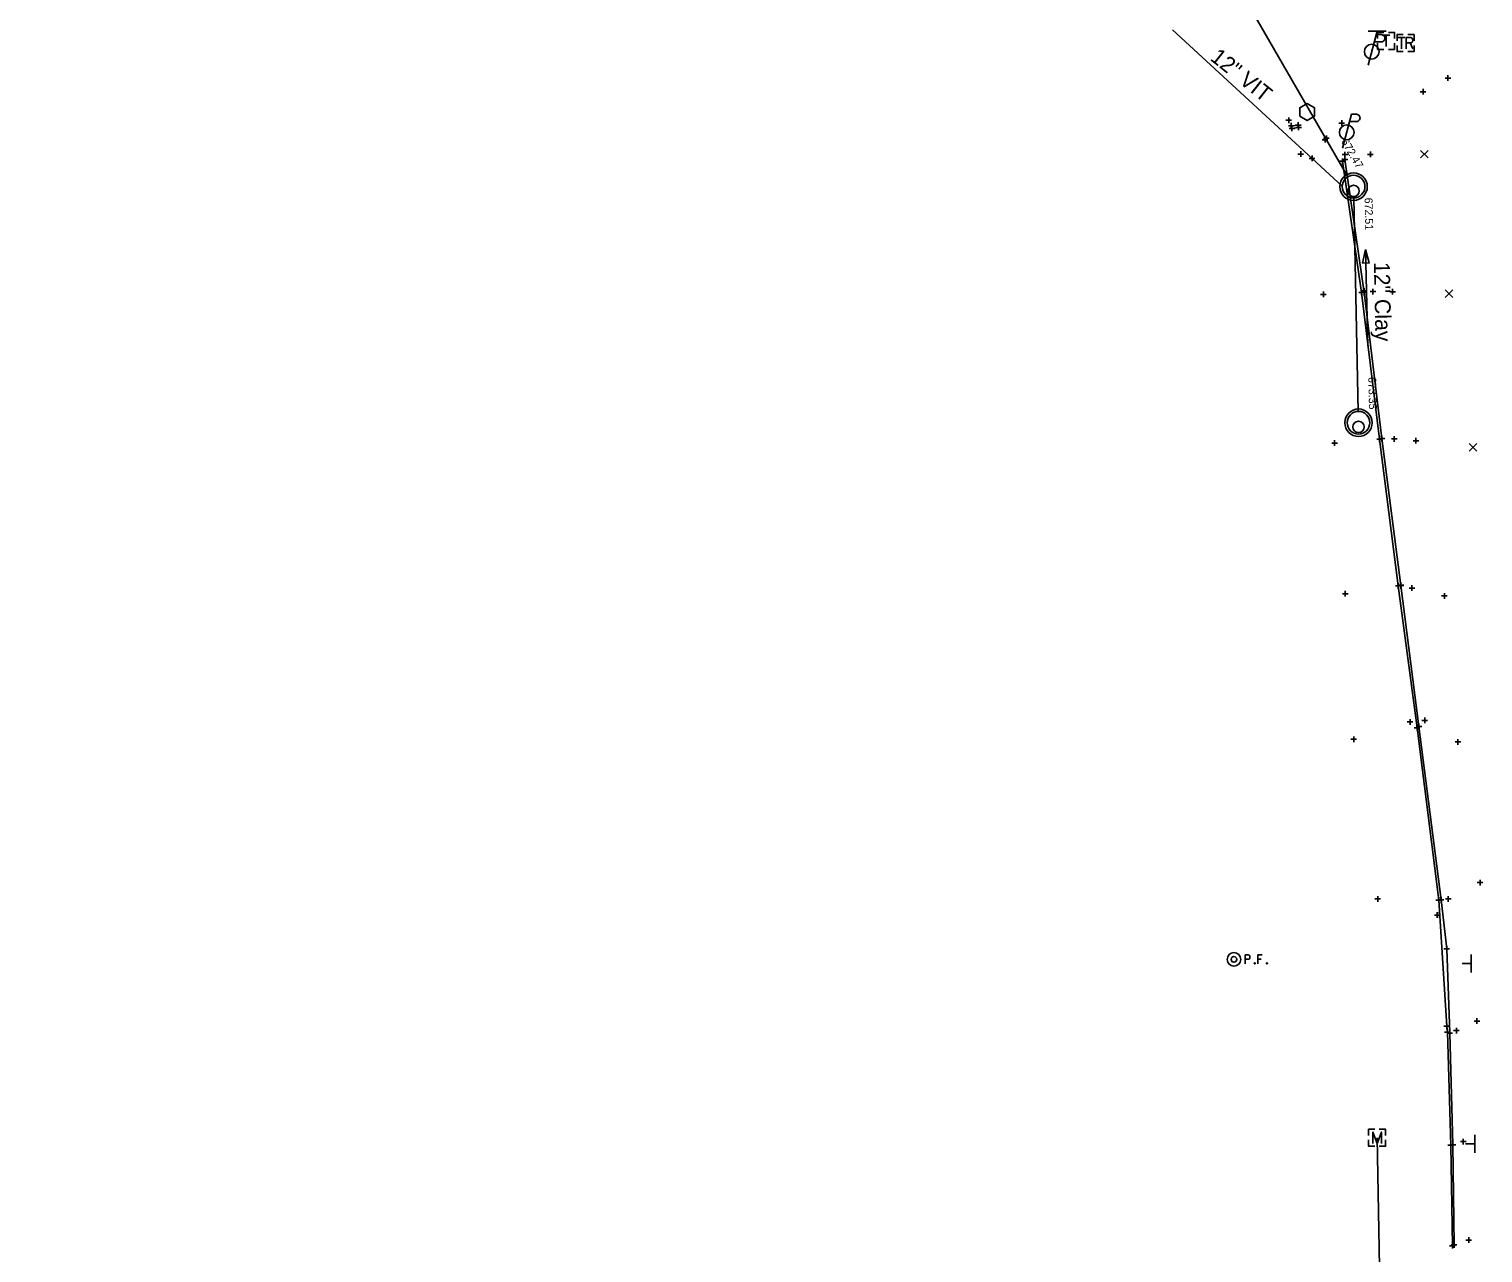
# Model space of a CAD drawing. Extents: x 2188719 to 2189819, y 654569 to 659504.
# Drawn here: x 2189309.7 to 2189566.5, y 658615.7 to 658831.7 of the extents above; entities that cross this region are included whole.
import ezdxf

# ---------------------------------------------------------------- set-up
doc = ezdxf.new("R2010")
doc.units = 0
for name, color, linetype in [('DR_X_Cells', 7, 'Continuous'), ('DR_X_Elev_Flow', 7, 'Continuous'), ('DR_X_Storm_Sewer', 7, 'Continuous'), ('DR_X_Text', 7, 'Continuous'), ('GK_Drainage_Nodes', 7, 'Continuous'), ('PV_X_Curb', 7, 'Continuous'), ('PV_X_EOP', 7, 'Continuous'), ('RD_X_Cells', 7, 'Continuous'), ('RW_X_CL_20', 7, 'Continuous'), ('SC_Scratch1', 7, 'Continuous'), ('SG_X_PullBox', 7, 'Continuous'), ('SN_X_Public', 7, 'Continuous'), ('SV_X_Mon_Cells_Found', 7, 'Continuous'), ('SV_X_Random_Point', 7, 'Continuous'), ('SV_X_Shot_Marker', 7, 'Continuous'), ('UT_X_Electric_Cells', 7, 'Continuous'), ('UT_X_Misc_Cells', 7, 'Continuous'), ('UT_X_Telecom_Cells', 7, 'Continuous')]:
    doc.layers.add(name, color=color, linetype=linetype)

msp = doc.modelspace()

# ---------------------------------------------------------------- linework, layer by layer
at = {"layer": 'DR_X_Cells'}
for centre, radius in [((2189543.62, 658803.9), 2.42), ((2189543.62, 658803.9), 2), ((2189543.62, 658803.15), 1), ((2189544.49, 658762.24), 2.42), ((2189544.49, 658762.24), 2), ((2189544.49, 658761.49), 1)]:
    msp.add_circle(centre, radius, dxfattribs=at)
at = {"layer": 'DR_X_Elev_Flow'}
for p, q in [((2189535.8, 658808.89), (2189536.8, 658808.89)), ((2189536.3, 658809.39), (2189536.3, 658808.39)), ((2189536.3, 658808.89), (2189536.3, 658808.89))]:
    msp.add_line(p, q, dxfattribs=at)
at = {"layer": 'DR_X_Storm_Sewer'}
for p, q in [((2189542.62, 658805.63), (2189309.74, 659209.07)), ((2189541.61, 658804), (2189511.65, 658831.56)), ((2189544.45, 658764.24), (2189543.67, 658801.9))]:
    msp.add_line(p, q, dxfattribs=at)
at = {"layer": 'DR_X_Text'}
msp.add_line((2189546.11, 658775.78), (2189545.75, 658792.83), dxfattribs=at)
msp.add_lwpolyline([(2189545.75, 658792.83), (2189546.4, 658790.44), (2189545.2, 658790.42)], close=True, dxfattribs=at)
at = {"layer": 'GK_Drainage_Nodes'}
for p, q in [((2189543.62, 658805.9), (2189543.62, 658805.9)), ((2189543.62, 658803.9), (2189543.62, 658803.9)), ((2189543.62, 658803.9), (2189543.62, 658803.9)), ((2189543.62, 658803.15), (2189543.62, 658803.15)), ((2189543.62, 658801.9), (2189543.62, 658801.9)), ((2189544.49, 658764.24), (2189544.49, 658764.24)), ((2189544.49, 658762.24), (2189544.49, 658762.24)), ((2189544.49, 658762.24), (2189544.49, 658762.24)), ((2189544.49, 658761.49), (2189544.49, 658761.49)), ((2189544.49, 658760.24), (2189544.49, 658760.24))]:
    msp.add_line(p, q, dxfattribs=at)
for centre in [(2189543.62, 658803.9), (2189544.49, 658762.24)]:
    msp.add_circle(centre, 2, dxfattribs=at)
at = {"layer": 'PV_X_Curb'}
for p, q in [((2189532.62, 658814.65), (2189533.85, 658814.75)), ((2189542.08, 658808.7), (2189545.46, 658785.19)), ((2189545.46, 658785.19), (2189548.63, 658759.43)), ((2189548.63, 658759.43), (2189551.97, 658733.5)), ((2189551.97, 658733.5), (2189555.16, 658708.6)), ((2189555.16, 658708.6), (2189559.07, 658678.03)), ((2189559.07, 658678.03), (2189560.08, 658669.38)), ((2189560.08, 658669.38), (2189560.61, 658654.53)), ((2189560.61, 658654.53), (2189561.17, 658634.82)), ((2189561.17, 658634.82), (2189561.36, 658617.13))]:
    msp.add_line(p, q, dxfattribs=at)
at = {"layer": 'PV_X_EOP'}
for p, q in [((2189532.74, 658814.18), (2189533.91, 658814.35)), ((2189541.67, 658808.39), (2189545.02, 658785.24)), ((2189545.02, 658785.24), (2189548.21, 658759.33)), ((2189548.21, 658759.33), (2189551.5, 658733.44)), ((2189551.5, 658733.44), (2189554.83, 658708.41)), ((2189554.83, 658708.41), (2189558.65, 658677.99)), ((2189558.65, 658677.99), (2189560.07, 658655.73)), ((2189560.07, 658655.73), (2189560.19, 658654.68)), ((2189560.19, 658654.68), (2189560.78, 658634.74)), ((2189560.78, 658634.74), (2189561.08, 658617))]:
    msp.add_line(p, q, dxfattribs=at)
at = {"layer": 'RD_X_Cells'}
msp.add_lwpolyline([(2189534.1, 658816.32), (2189535.4, 658815.57), (2189536.7, 658816.32), (2189536.7, 658817.82), (2189535.4, 658818.57), (2189534.1, 658817.82), (2189534.1, 658816.32)], dxfattribs=at)
at = {"layer": 'RW_X_CL_20'}
msp.add_line((2189557.93, 658099.21), (2189547.77, 658636.04), dxfattribs=at)
at = {"layer": 'SG_X_PullBox'}
msp.add_line((2189552.79, 658829.23), (2189552.79, 658829.23), dxfattribs=at)
for points in [[(2189552.39, 658830.73), (2189551.29, 658830.73), (2189551.29, 658829.63)], [(2189551.29, 658828.83), (2189551.29, 658827.73), (2189552.39, 658827.73)], [(2189551.44, 658830.23), (2189552.68, 658830.23)], [(2189552.07, 658830.23), (2189552.07, 658828.23)], [(2189552.9, 658828.23), (2189552.9, 658830.23), (2189553.66, 658830.23), (2189553.74, 658830.21), (2189553.85, 658830.18), (2189553.9, 658830.15), (2189553.94, 658830.12), (2189554.01, 658830.04), (2189554.05, 658829.96), (2189554.08, 658829.83), (2189554.08, 658829.65), (2189554.07, 658829.58), (2189554.04, 658829.49), (2189553.97, 658829.38), (2189553.91, 658829.33), (2189553.86, 658829.3), (2189553.83, 658829.28), (2189553.79, 658829.27), (2189553.64, 658829.25), (2189552.9, 658829.25)], [(2189554.29, 658829.63), (2189554.29, 658830.73), (2189553.19, 658830.73)], [(2189553.19, 658827.73), (2189554.29, 658827.73), (2189554.29, 658828.83)], [(2189553.64, 658829.25), (2189554.08, 658828.23)]]:
    msp.add_lwpolyline(points, dxfattribs=at)
at = {"layer": 'SN_X_Public'}
for p, q in [((2189564.38, 658668.42), (2189564.38, 658665.22)), ((2189564.38, 658666.82), (2189562.78, 658666.82)), ((2189565.01, 658636.57), (2189565.01, 658633.37)), ((2189565.01, 658634.97), (2189563.41, 658634.97))]:
    msp.add_line(p, q, dxfattribs=at)
at = {"layer": 'SV_X_Mon_Cells_Found'}
msp.add_line((2189547.77, 658636.04), (2189547.77, 658636.04), dxfattribs=at)
for points in [[(2189524.49, 658666.73), (2189524.49, 658668.33), (2189525.02, 658668.33), (2189525.08, 658668.32), (2189525.15, 658668.29), (2189525.19, 658668.26), (2189525.22, 658668.24), (2189525.26, 658668.18), (2189525.3, 658668.11), (2189525.32, 658668.01), (2189525.32, 658667.86), (2189525.31, 658667.81), (2189525.29, 658667.74), (2189525.24, 658667.65), (2189525.2, 658667.61), (2189525.16, 658667.58), (2189525.11, 658667.56), (2189525.02, 658667.55), (2189524.49, 658667.55)], [(2189526.13, 658666.94), (2189526.19, 658666.94), (2189526.22, 658666.92), (2189526.26, 658666.87), (2189526.26, 658666.8), (2189526.22, 658666.75), (2189526.19, 658666.73), (2189526.13, 658666.73), (2189526.1, 658666.75), (2189526.07, 658666.8), (2189526.07, 658666.87), (2189526.1, 658666.92), (2189526.13, 658666.94)], [(2189527.5, 658668.33), (2189526.74, 658668.33), (2189526.74, 658666.73)], [(2189526.74, 658667.55), (2189527.28, 658667.55)], [(2189528.28, 658666.94), (2189528.34, 658666.94), (2189528.37, 658666.92), (2189528.41, 658666.87), (2189528.41, 658666.8), (2189528.37, 658666.75), (2189528.34, 658666.73), (2189528.28, 658666.73), (2189528.25, 658666.75), (2189528.22, 658666.8), (2189528.22, 658666.87), (2189528.25, 658666.92), (2189528.28, 658666.94)], [(2189546.27, 658636.42), (2189546.27, 658637.54), (2189547.4, 658637.54)], [(2189547.04, 658635.04), (2189547.04, 658637.04), (2189547.77, 658635.04), (2189548.52, 658637.04), (2189548.52, 658635.04)], [(2189548.13, 658637.54), (2189549.28, 658637.54), (2189549.28, 658636.42)], [(2189547.4, 658634.54), (2189546.27, 658634.54), (2189546.27, 658635.66)], [(2189549.28, 658635.66), (2189549.28, 658634.54), (2189548.13, 658634.54)]]:
    msp.add_lwpolyline(points, dxfattribs=at)
for centre, radius in [((2189522.5, 658667.53), 1.2), ((2189522.49, 658667.53), 0.495)]:
    msp.add_circle(centre, radius, dxfattribs=at)
at = {"layer": 'SV_X_Random_Point'}
for p, q in [((2189555.43, 658808.96), (2189556.77, 658810.29)), ((2189555.43, 658810.29), (2189556.77, 658808.96)), ((2189559.78, 658784.36), (2189561.12, 658785.7)), ((2189559.78, 658785.7), (2189561.12, 658784.36)), ((2189564.03, 658757.23), (2189565.36, 658758.57)), ((2189564.03, 658758.57), (2189565.36, 658757.23))]:
    msp.add_line(p, q, dxfattribs=at)
at = {"layer": 'SV_X_Shot_Marker'}
for p, q in [((2189560.29, 658823.56), (2189560.29, 658822.56)), ((2189555.89, 658821.16), (2189555.89, 658820.16)), ((2189559.79, 658823.06), (2189560.79, 658823.06)), ((2189560.29, 658823.06), (2189560.29, 658823.06)), ((2189555.39, 658820.66), (2189556.39, 658820.66)), ((2189555.89, 658820.66), (2189555.89, 658820.66)), ((2189532.18, 658816.13), (2189532.18, 658815.13)), ((2189531.68, 658815.63), (2189532.68, 658815.63)), ((2189532.12, 658814.65), (2189533.12, 658814.65)), ((2189532.18, 658815.63), (2189532.18, 658815.63)), ((2189532.24, 658814.18), (2189533.24, 658814.18)), ((2189532.62, 658815.15), (2189532.62, 658814.15)), ((2189532.62, 658814.65), (2189532.62, 658814.65)), ((2189532.74, 658814.68), (2189532.74, 658813.68)), ((2189532.74, 658814.18), (2189532.74, 658814.18)), ((2189533.35, 658814.75), (2189534.35, 658814.75)), ((2189533.41, 658814.35), (2189534.41, 658814.35)), ((2189533.85, 658815.25), (2189533.85, 658814.25)), ((2189533.85, 658814.75), (2189533.85, 658814.75)), ((2189533.91, 658814.85), (2189533.91, 658813.85)), ((2189533.91, 658814.35), (2189533.91, 658814.35)), ((2189541.03, 658815.12), (2189542.03, 658815.12)), ((2189541.53, 658815.62), (2189541.53, 658814.62)), ((2189541.53, 658815.12), (2189541.53, 658815.12)), ((2189538.1, 658812.17), (2189539.1, 658812.17)), ((2189538.33, 658812.43), (2189539.33, 658812.43)), ((2189538.6, 658812.67), (2189538.6, 658811.67)), ((2189538.6, 658812.17), (2189538.6, 658812.17)), ((2189538.83, 658812.93), (2189538.83, 658811.93)), ((2189538.83, 658812.43), (2189538.83, 658812.43)), ((2189533.8, 658809.64), (2189534.8, 658809.64)), ((2189534.3, 658810.14), (2189534.3, 658809.14)), ((2189534.3, 658809.64), (2189534.3, 658809.64)), ((2189541.17, 658808.39), (2189542.17, 658808.39)), ((2189541.58, 658808.7), (2189542.58, 658808.7)), ((2189541.6, 658809.57), (2189542.6, 658809.57)), ((2189541.67, 658808.89), (2189541.67, 658807.89)), ((2189541.67, 658808.39), (2189541.67, 658808.39)), ((2189542.08, 658809.2), (2189542.08, 658808.2)), ((2189542.08, 658808.7), (2189542.08, 658808.7)), ((2189542.1, 658810.07), (2189542.1, 658809.07)), ((2189542.1, 658809.57), (2189542.1, 658809.57)), ((2189546.1, 658809.59), (2189547.1, 658809.59)), ((2189546.1, 658809.59), (2189547.1, 658809.59)), ((2189546.6, 658810.09), (2189546.6, 658809.09)), ((2189546.6, 658810.09), (2189546.6, 658809.09)), ((2189546.6, 658809.59), (2189546.6, 658809.59)), ((2189546.6, 658809.59), (2189546.6, 658809.59)), ((2189538.3, 658785.37), (2189538.3, 658784.37)), ((2189544.52, 658785.24), (2189545.52, 658785.24)), ((2189544.96, 658785.19), (2189545.96, 658785.19)), ((2189544.98, 658785.49), (2189545.98, 658785.49)), ((2189545.02, 658785.74), (2189545.02, 658784.74)), ((2189545.02, 658785.24), (2189545.02, 658785.24)), ((2189545.46, 658785.69), (2189545.46, 658784.69)), ((2189545.46, 658785.19), (2189545.46, 658785.19)), ((2189545.48, 658785.99), (2189545.48, 658784.99)), ((2189545.48, 658785.49), (2189545.48, 658785.49)), ((2189546.52, 658785.37), (2189547.52, 658785.37)), ((2189547.02, 658785.87), (2189547.02, 658784.87)), ((2189547.02, 658785.37), (2189547.02, 658785.37)), ((2189550.01, 658785.36), (2189551.01, 658785.36)), ((2189550.01, 658785.36), (2189551.01, 658785.36)), ((2189550.51, 658785.86), (2189550.51, 658784.86)), ((2189550.51, 658785.86), (2189550.51, 658784.86)), ((2189550.51, 658785.36), (2189550.51, 658785.36)), ((2189550.51, 658785.36), (2189550.51, 658785.36)), ((2189537.8, 658784.87), (2189538.8, 658784.87)), ((2189538.3, 658784.87), (2189538.3, 658784.87)), ((2189547.71, 658759.33), (2189548.71, 658759.33)), ((2189547.72, 658759.31), (2189548.72, 658759.31)), ((2189548.13, 658759.43), (2189549.13, 658759.43)), ((2189548.21, 658759.83), (2189548.21, 658758.83)), ((2189548.21, 658759.33), (2189548.21, 658759.33)), ((2189548.22, 658759.81), (2189548.22, 658758.81)), ((2189548.22, 658759.31), (2189548.22, 658759.31)), ((2189548.63, 658759.93), (2189548.63, 658758.93)), ((2189548.63, 658759.43), (2189548.63, 658759.43)), ((2189550.3, 658759.37), (2189551.3, 658759.37)), ((2189550.8, 658759.87), (2189550.8, 658758.87)), ((2189550.8, 658759.37), (2189550.8, 658759.37)), ((2189554.64, 658759.55), (2189554.64, 658758.55)), ((2189554.64, 658759.55), (2189554.64, 658758.55)), ((2189539.76, 658758.65), (2189540.76, 658758.65)), ((2189540.26, 658759.15), (2189540.26, 658758.15)), ((2189540.26, 658758.65), (2189540.26, 658758.65)), ((2189554.14, 658759.05), (2189555.14, 658759.05)), ((2189554.14, 658759.05), (2189555.14, 658759.05)), ((2189554.64, 658759.05), (2189554.64, 658759.05)), ((2189554.64, 658759.05), (2189554.64, 658759.05)), ((2189551.5, 658733.94), (2189551.5, 658732.94)), ((2189551.97, 658734.07), (2189551.97, 658733.07)), ((2189551.97, 658734), (2189551.97, 658733)), ((2189541.65, 658732.06), (2189542.65, 658732.06)), ((2189542.15, 658732.56), (2189542.15, 658731.56)), ((2189542.15, 658732.06), (2189542.15, 658732.06)), ((2189551, 658733.44), (2189552, 658733.44)), ((2189551.47, 658733.57), (2189552.47, 658733.57)), ((2189551.47, 658733.5), (2189552.47, 658733.5)), ((2189551.5, 658733.44), (2189551.5, 658733.44)), ((2189551.97, 658733.57), (2189551.97, 658733.57)), ((2189551.97, 658733.5), (2189551.97, 658733.5)), ((2189553.43, 658733.06), (2189554.43, 658733.06)), ((2189553.93, 658733.56), (2189553.93, 658732.56)), ((2189553.93, 658733.06), (2189553.93, 658733.06)), ((2189559.15, 658731.68), (2189560.15, 658731.68)), ((2189559.15, 658731.68), (2189560.15, 658731.68)), ((2189559.65, 658732.18), (2189559.65, 658731.18)), ((2189559.65, 658732.18), (2189559.65, 658731.18)), ((2189559.65, 658731.68), (2189559.65, 658731.68)), ((2189559.65, 658731.68), (2189559.65, 658731.68)), ((2189553.1, 658709.43), (2189554.1, 658709.43)), ((2189553.6, 658709.93), (2189553.6, 658708.93)), ((2189553.6, 658709.43), (2189553.6, 658709.43)), ((2189554.33, 658708.41), (2189555.33, 658708.41)), ((2189554.66, 658708.6), (2189555.66, 658708.6)), ((2189554.83, 658708.91), (2189554.83, 658707.91)), ((2189554.83, 658708.41), (2189554.83, 658708.41)), ((2189555.16, 658709.1), (2189555.16, 658708.1)), ((2189555.16, 658708.6), (2189555.16, 658708.6)), ((2189555.69, 658709.7), (2189556.69, 658709.7)), ((2189556.19, 658710.2), (2189556.19, 658709.2)), ((2189556.19, 658709.7), (2189556.19, 658709.7)), ((2189543.14, 658706.37), (2189544.14, 658706.37)), ((2189543.64, 658706.87), (2189543.64, 658705.87)), ((2189543.64, 658706.37), (2189543.64, 658706.37)), ((2189561.53, 658705.92), (2189562.53, 658705.92)), ((2189561.53, 658705.92), (2189562.53, 658705.92)), ((2189562.03, 658706.42), (2189562.03, 658705.42)), ((2189562.03, 658706.42), (2189562.03, 658705.42)), ((2189562.03, 658705.92), (2189562.03, 658705.92)), ((2189562.03, 658705.92), (2189562.03, 658705.92)), ((2189565.46, 658681.09), (2189566.46, 658681.09)), ((2189565.96, 658681.59), (2189565.96, 658680.59)), ((2189565.96, 658681.09), (2189565.96, 658681.09)), ((2189547.4, 658678.19), (2189548.4, 658678.19)), ((2189547.9, 658678.69), (2189547.9, 658677.69)), ((2189547.9, 658678.19), (2189547.9, 658678.19)), ((2189558.15, 658677.99), (2189559.15, 658677.99)), ((2189558.57, 658678.03), (2189559.57, 658678.03)), ((2189558.65, 658678.49), (2189558.65, 658677.49)), ((2189558.65, 658677.99), (2189558.65, 658677.99)), ((2189559.07, 658678.53), (2189559.07, 658677.53)), ((2189559.07, 658678.03), (2189559.07, 658678.03)), ((2189559.84, 658678.2), (2189560.84, 658678.2)), ((2189560.34, 658678.7), (2189560.34, 658677.7)), ((2189560.34, 658678.2), (2189560.34, 658678.2)), ((2189557.9, 658675.36), (2189558.9, 658675.36)), ((2189557.94, 658675.34), (2189558.94, 658675.34)), ((2189558.4, 658675.86), (2189558.4, 658674.86)), ((2189558.4, 658675.36), (2189558.4, 658675.36)), ((2189558.44, 658675.84), (2189558.44, 658674.84)), ((2189558.44, 658675.34), (2189558.44, 658675.34)), ((2189560.08, 658669.88), (2189560.08, 658668.88)), ((2189559.58, 658669.38), (2189560.58, 658669.38)), ((2189560.08, 658669.38), (2189560.08, 658669.38)), ((2189564.89, 658656.64), (2189565.89, 658656.64)), ((2189565.39, 658657.14), (2189565.39, 658656.14)), ((2189565.39, 658656.64), (2189565.39, 658656.64)), ((2189559.57, 658655.73), (2189560.57, 658655.73)), ((2189559.69, 658654.68), (2189560.69, 658654.68)), ((2189560.07, 658656.23), (2189560.07, 658655.23)), ((2189560.07, 658655.73), (2189560.07, 658655.73)), ((2189560.11, 658654.53), (2189561.11, 658654.53)), ((2189560.19, 658655.18), (2189560.19, 658654.18)), ((2189560.19, 658654.68), (2189560.19, 658654.68)), ((2189560.61, 658655.03), (2189560.61, 658654.03)), ((2189560.61, 658654.53), (2189560.61, 658654.53)), ((2189561.29, 658654.95), (2189562.29, 658654.95)), ((2189561.79, 658655.45), (2189561.79, 658654.45)), ((2189561.79, 658654.95), (2189561.79, 658654.95)), ((2189560.28, 658634.74), (2189561.28, 658634.74)), ((2189560.67, 658634.82), (2189561.67, 658634.82)), ((2189560.78, 658635.24), (2189560.78, 658634.24)), ((2189560.78, 658634.74), (2189560.78, 658634.74)), ((2189561.17, 658635.32), (2189561.17, 658634.32)), ((2189561.17, 658634.82), (2189561.17, 658634.82)), ((2189562.48, 658635.38), (2189563.48, 658635.38)), ((2189562.98, 658635.88), (2189562.98, 658634.88)), ((2189562.98, 658635.38), (2189562.98, 658635.38)), ((2189563.96, 658618.49), (2189563.96, 658617.49)), ((2189560.58, 658617), (2189561.58, 658617)), ((2189560.86, 658617.13), (2189561.86, 658617.13)), ((2189561.08, 658617.5), (2189561.08, 658616.5)), ((2189561.08, 658617), (2189561.08, 658617)), ((2189561.36, 658617.63), (2189561.36, 658616.63)), ((2189561.36, 658617.13), (2189561.36, 658617.13)), ((2189563.46, 658617.99), (2189564.46, 658617.99)), ((2189563.96, 658617.99), (2189563.96, 658617.99))]:
    msp.add_line(p, q, dxfattribs=at)
at = {"layer": 'UT_X_Electric_Cells'}
for p, q in [((2189543.27, 658816.68), (2189541.66, 658810.68)), ((2189543.27, 658816.68), (2189544.12, 658816.68)), ((2189542.92, 658815.4), (2189544.12, 658815.4))]:
    msp.add_line(p, q, dxfattribs=at)
msp.add_circle((2189542.41, 658813.48), 1.3, dxfattribs=at)
msp.add_arc((2189544.13, 658816.04), 0.638, 268.8767, 91.1233, dxfattribs=at)
at = {"layer": 'UT_X_Misc_Cells'}
for p, q in [((2189549.39, 658831.32), (2189546.19, 658831.32)), ((2189547.79, 658831.32), (2189546.19, 658825.32)), ((2189547.29, 658829.45), (2189548.48, 658829.45)), ((2189547.63, 658830.72), (2189548.48, 658830.72))]:
    msp.add_line(p, q, dxfattribs=at)
msp.add_circle((2189546.83, 658827.72), 1.3, dxfattribs=at)
msp.add_arc((2189548.5, 658830.09), 0.638, 268.8767, 91.1233, dxfattribs=at)
at = {"layer": 'UT_X_Telecom_Cells'}
for p, q in [((2189548.72, 658830.63), (2189550.02, 658830.63)), ((2189549.37, 658828.63), (2189549.37, 658830.63)), ((2189549.37, 658829.63), (2189549.37, 658829.63))]:
    msp.add_line(p, q, dxfattribs=at)
for points in [[(2189548.97, 658831.13), (2189547.87, 658831.13), (2189547.87, 658830.03)], [(2189547.87, 658829.23), (2189547.87, 658828.13), (2189548.97, 658828.13)], [(2189550.87, 658830.03), (2189550.87, 658831.13), (2189549.77, 658831.13)], [(2189549.77, 658828.13), (2189550.87, 658828.13), (2189550.87, 658829.23)]]:
    msp.add_lwpolyline(points, dxfattribs=at)

# ---------------------------------------------------------------- texts
at = {"layer": 'DR_X_Text'}
for s, rotation, p in [('12" VIT', 321.4509, (2189518.13, 658826.35)), ('12" Clay', 271.1907, (2189547.2, 658790.58))]:
    msp.add_text(s, height=2.8, rotation=rotation, dxfattribs=at).set_placement(p)
at = {"layer": 'SC_Scratch1'}
for s, rotation, p in [('672.47', 299.9954, (2189541.35, 658811.89)), ('672.51', 271.1907, (2189545.57, 658801.94)), ('673.35', 271.1907, (2189546.22, 658770.29))]:
    msp.add_text(s, height=1.4, rotation=rotation, dxfattribs=at).set_placement(p)

doc.saveas('drawing.dxf')
